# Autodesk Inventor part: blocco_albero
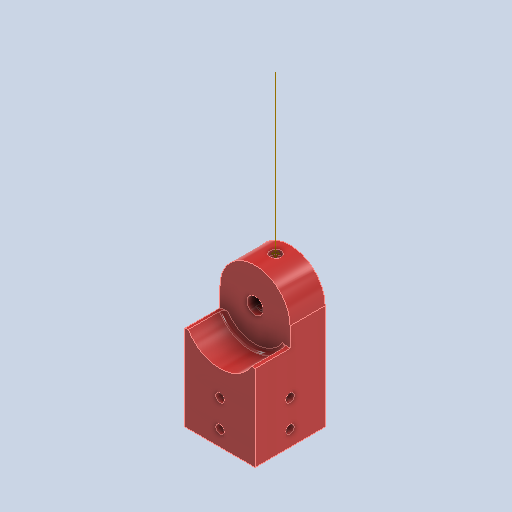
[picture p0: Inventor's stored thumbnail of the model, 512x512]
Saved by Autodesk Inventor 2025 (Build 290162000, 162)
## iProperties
Created: 2026-01
Part Number: blocco_albero
Material: Plastica ABS
Document SubType Name: Modeling
Designer: R5800u
Density: 1.06 g/cm^3
Appearance: Rosso arancio
Author: R5800u
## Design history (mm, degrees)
sketch "Schizzo1"
  geometry: L1 (-4.944, -3.1)-(4.944, -3.1); L2 (4.944, -3.1)-(4.944, 3.1); L3 (4.944, 3.1)-(-4.944, 3.1); L4 (-4.944, 3.1)-(-4.944, -3.1); L5 (-4.944, -3.1)-(4.944, 3.1); L6 (4.944, -3.1)-(-4.944, 3.1); C1 r 4.1 at (0, 0); C2 r 18 at (0, 0); 5 further points
  constraints: 12 end point, 2 centre point, 2 coincident, 2 midpoint, 2 parallel, 1 horizontal, 1 perpendicular
  dimensions: "d0" = 8.2 diameter of C1; "d1" = 6.2 distance of L2.end L1.end; "d2" = 36 diameter of C2
extrude "Estrusione1" new body sketch "Schizzo1" distance "d3" = 18; taper "d4" = 0 deg
sketch "Schizzo8"
  geometry: A1 r 4.1 centre (0, 0) between (2.683, -3.1) and (2.683, 3.1) reference; 3 further points
  constraints: 1 coincident, 3 other
extrude "Estrusione6" cut sketch "Schizzo8" distance "d39" = 3; taper "d40" = 0 deg
sketch "Schizzo9"
  geometry: L1 (18, 18)-(-18, 18); L2 (-18, 18)-(-18, -18); L3 (-18, -18)-(18, -18); L4 (18, -18)-(18, 18); L5 (18, 18)-(-18, -18); L6 (-18, 18)-(18, -18); L7 (2.683, 3.1)-(-2.683, 3.1) reference; L8 (-2.683, -3.1)-(2.683, -3.1) reference; L9 (18, -54)-(18, -18); L10 (-18, -18)-(18, -18); L11 (18, -18)-(18, -54); L12 (18, -54)-(-18, -54); L13 (-18, -54)-(-18, -18); C1 r 18 at (0, 0) reference; A1 r 4.1 centre (0, 0) between (-2.683, 3.1) and (-2.683, -3.1) reference; A2 r 4.1 centre (0, 0) between (-2.683, 3.1) and (-2.683, -3.1) reference; A3 r 4.1 centre (0, 0) between (2.683, -3.1) and (2.683, 3.1) reference; 6 further points
  constraints: 22 end point, 4 parallel, 2 horizontal, 2 midpoint, 2 perpendicular, 2 point on line
  dimensions: "d41" = 36 distance of L3.end L2.end; "d42" = 36 distance of L2.end L1.end; "d82" = 36 distance of L12.end L10.start
extrude "Estrusione7" join sketch "Schizzo9" distance "d44" = 36; taper "d45" = 0 deg
chamfer "Smusso2" distance "d46" = 10; stored, may be unused: second distance "d47" = 2, angle "d48" = 45 deg
sketch "Schizzo11"
  geometry: C1 r 18 at (0, 0) reference; C2 r 19 at (0, 0); 1 further point
  constraints: 1 centre point
  dimensions: "d57" = 1 radial gap between concentric circles of C1 C2
extrude "Estrusione9" cut sketch "Schizzo11" stored distance "d58" = 36; taper "d59" = 0 deg
fillet "Raccordo5" dims "d60" = 2
node "Piano di lavoro4"
sketch "Schizzo14"
  geometry: L1 (0.698, 36)-(33.302, 36) reference; L2 (17, 36)-(17, 18); L3 (2.87, 18)-(31.13, 18) reference; L4 (6.9, 28.1)-(27.1, 28.1); L5 (27.1, 28.1)-(27.1, 7.9); L6 (27.1, 7.9)-(6.9, 7.9); L7 (6.9, 7.9)-(6.9, 28.1); L8 (6.9, 28.1)-(27.1, 7.9); L9 (27.1, 28.1)-(6.9, 7.9); 1 further point
  constraints: 14 end point, 4 midpoint, 2 parallel, 1 horizontal, 1 perpendicular
  dimensions: "d83" = 18 distance of L2.start L2.end (derived); "d84" = 20.2 distance of L5.end L6.end; "d85" = 20.2 distance of L4.end L5.end
extrude "Estrusione10" cut sketch "Schizzo14" distance "d86" = 30; taper "d87" = 0 deg
sketch "Schizzo12"
  geometry: L1 (-18, -54)-(18, -54) reference; L2 (0, -54)-(0, -24); L3 (-10.1, -24)-(10.1, -24) reference; 5 further points
  constraints: 2 end point, 2 midpoint, 2 point on line
  dimensions: "d88" = 8 distance from line of L1 point (0, -46); "d89" = 8 distance from line of L3 point (0, -32)
hole "Foro2" sketch "Schizzo12" at (0, -46), (0, -32) diameter "d66" = 4.3; stored, may be unused: countersink angle "d70" = 90 deg, drill point angle "d72" = 118 deg; dims "d67" = 6, "d68" = 9.4, "d69" = 2, "d71" = 10
sketch "Schizzo13"
  geometry: L1 (-18, -44)-(18, -44) reference; L2 (0, 0)-(18, 0) reference; L3 (0, 10)-(0, 0) reference; L4 (-18, 10)-(0, 10) reference; L5 (0, -44)-(0, -14); L6 (10.1, -14)-(-10.1, -14) reference; L7 (-18, -44)-(-18, 10) reference; L8 (18, 0)-(18, -44) reference; 3 further points
  constraints: 2 end point, 2 midpoint, 2 point on line
  dimensions: "d73" = 8 distance from line of L1 point (0, -36); "d74" = 8 distance from line of L6 point (0, -22)
hole "Foro3" sketch "Schizzo13" at (0, -36), (0, -22) diameter "d75" = 4.3; stored, may be unused: countersink angle "d79" = 90 deg, drill point angle "d81" = 118 deg; dims "d76" = 6, "d77" = 4, "d78" = 2, "d80" = 8
sketch "Schizzo15"
  geometry: L1 (2.683, 0)-(2.683, 15); L2 (0, 15)-(5.367, 15) reference; 1 further point
  constraints: 2 end point, 2 midpoint
hole "Foro4" sketch "Schizzo15" at (2.683, 7.5) diameter "d90" = 3.2; stored, may be unused: countersink angle "d94" = 90 deg, drill point angle "d96" = 118 deg; dims "d91" = 6, "d92" = 6.3, "d93" = 2, "d95" = 8
node "Piano di lavoro1"
sketch "Schizzo16"
  geometry: C1 r 2.85 at (0, 7.5); 2 further points
  constraints: 1 centre point, 1 other
  dimensions: "d108" = 5.7 diameter of C1
node "Punto di riferimento1"
node "Asse di lavoro1"
hole "Foro5" diameter "d99" = 3.2; stored, may be unused: countersink angle "d103" = 90 deg, drill point angle "d105" = 118 deg; dims "d100" = 6, "d101" = 5.7, "d102" = 2.6, "d104" = 8, "d106" = 10, "d107" = 10
extrude "Estrusione11" cut sketch "Schizzo16" stored distance "d109" = 1; taper "d110" = 0 deg
sketch "Schizzo17"
  geometry: L1 (-2.683, 3.1)-(2.683, 3.1) reference; L2 (0, 3.1)-(0, 8.1); L3 (-3.15, 6.75)-(3.15, 6.75); L4 (3.15, 6.75)-(3.15, 9.45); L5 (3.15, 9.45)-(-3.15, 9.45); L6 (-3.15, 9.45)-(-3.15, 6.75); L7 (-3.15, 6.75)-(3.15, 9.45); L8 (3.15, 6.75)-(-3.15, 9.45); 1 further point
  constraints: 14 end point, 3 midpoint, 2 parallel, 1 horizontal, 1 perpendicular, 1 vertical
  dimensions: "d112" = 5 distance of L2.start L2.end; "d113" = 6.3 distance of L5.end L4.end; "d114" = 2.7 distance of L4.end L3.end
extrude "Estrusione12" cut sketch "Schizzo17" distance "d115" = 13; taper "d116" = 0 deg
node "Solido1"
node "Linea chiusa proiettata5"
node "Riferimento1"
node "Linea chiusa proiettata7"
